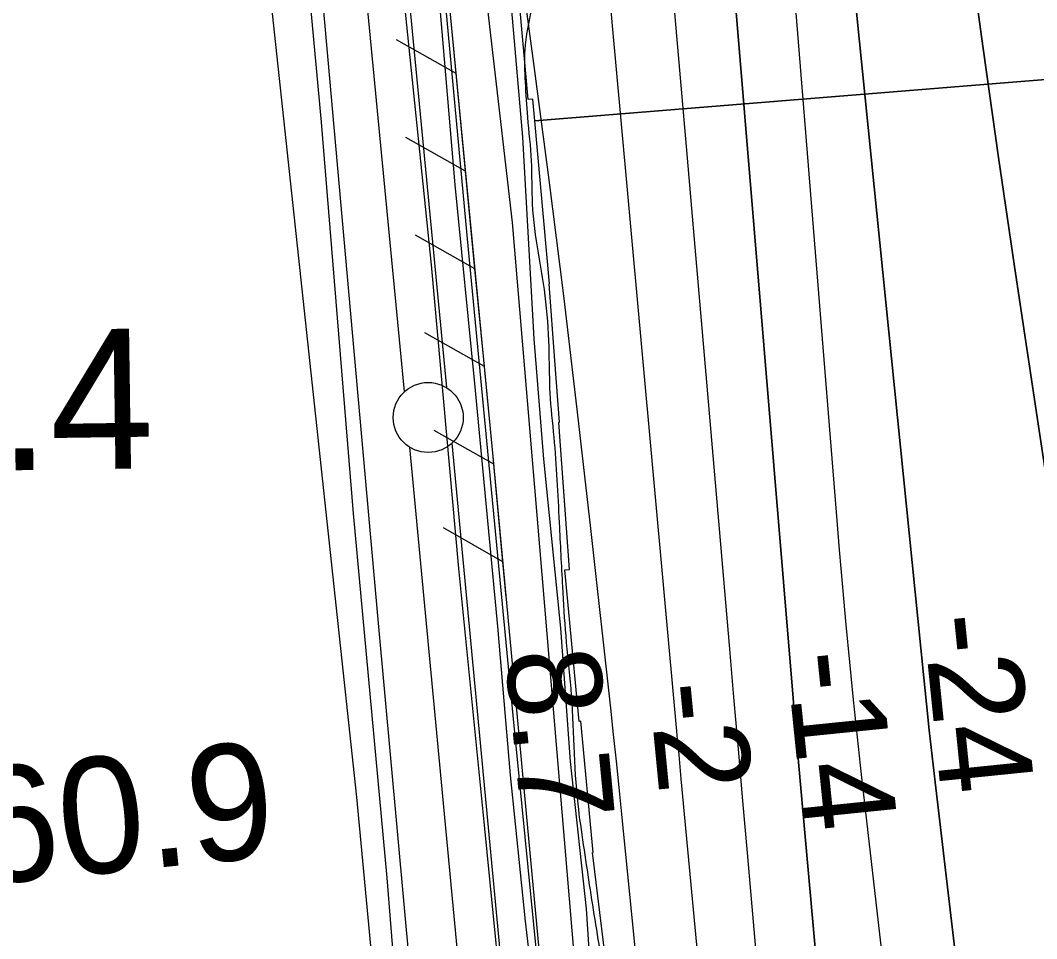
# Model space of a CAD drawing. Extents: x 3694830 to 3732949, y 415201 to 440970.
# Drawn here: x 3715556 to 3716283, y 426007 to 426663 of the extents above; entities that cross this region are included whole.
import ezdxf

# ---------------------------------------------------------------- set-up
doc = ezdxf.new("R2010")
doc.units = 0
for name, color, linetype in [('V-FLOD-BASE', 7, 'Continuous'), ('V-LEVE-TOET', 7, 'Continuous'), ('V-RAIL-TRAK', 7, 'Continuous'), ('V-RIVR-EDGE', 7, 'Continuous'), ('V-RIVR-RANG', 7, 'Continuous'), ('V-RIVR-RANG-IDEN', 7, 'Continuous'), ('V-RRAP-FSHR', 7, 'Continuous'), ('V-RRAP-RVMT', 7, 'Continuous'), ('V-SITE-VEGE', 7, 'Continuous'), ('V-SURV-IDEN', 7, 'Continuous'), ('V-SURV-LINE', 7, 'Continuous'), ('V-TOPO-DPTH', 7, 'Continuous'), ('V-TOPO-MINR', 7, 'Continuous'), ('V-TOPO-WATR', 7, 'Continuous')]:
    doc.layers.add(name, color=color, linetype=linetype)

msp = doc.modelspace()

# ---------------------------------------------------------------- linework, layer by layer
at = {"layer": 'V-FLOD-BASE'}
msp.add_lwpolyline([(3715905.18, 425914.44), (3715887.74, 426090.15), (3715869.81, 426271.15), (3715850.1, 426488.12), (3715831.64, 426668.6), (3715818.42, 426842.69), (3715797.31, 427023.2), (3715781.05, 427212.11), (3715763.21, 427402.63), (3715742.39, 427614.33)], dxfattribs=at)
at = {"layer": 'V-LEVE-TOET'}
for points in [[(3715835.07, 425981.72), (3715811.98, 426234.68), (3715789.9, 426482.35), (3715764.95, 426762.82), (3715743.66, 426980.87), (3715719.56, 427239.13), (3715695.46, 427496.33), (3715669.46, 427778.93)], [(3715760.27, 427687.76), (3715769.43, 427589.85), (3715783.49, 427449.6), (3715793.96, 427321.54), (3715804.19, 427224.16), (3715805.95, 427185.01), (3715809.84, 427147.96), (3715816.68, 427086.03), (3715821.57, 427042.1), (3715826.34, 426984.42), (3715834.02, 426898.69), (3715840.22, 426824.6), (3715841.49, 426789.69), (3715846.98, 426753.16), (3715855.78, 426674.29), (3715866.77, 426545.17), (3715880.82, 426403.33), (3715897.23, 426229.75), (3715906.31, 426123.38), (3715917, 426019.12), (3715930.25, 425906.89)]]:
    msp.add_lwpolyline(points, dxfattribs=at)
at = {"layer": 'V-RAIL-TRAK'}
msp.add_lwpolyline([(3715607.74, 428367.03), (3715620.36, 428242.12), (3715640.52, 428016.68), (3715666.47, 427729.85), (3715694.47, 427434.54), (3715722.17, 427107.51), (3715752.15, 426798.43), (3715771.41, 426589.92), (3715794.26, 426310.52), (3715818.34, 426050.15), (3715838.28, 425800.39), (3715839.84, 425780), (3715843.96, 425726.31), (3715860.4, 425556.95), (3715875.68, 425375.97), (3715892.06, 425199.21), (3715907.36, 425021.41), (3715920.89, 424880.63), (3715944.12, 424642.47), (3715965.27, 424409.62), (3715982.46, 424206.42)], dxfattribs=at)
at = {"layer": 'V-RIVR-EDGE'}
msp.add_spline([(3715510.15, 429495), (3715519.36, 429459.39), (3715532.61, 429419.73), (3715534.19, 429405.98), (3715534.58, 429397.89), (3715533.76, 429394.66), (3715530.11, 429389.82), (3715520.8, 429385.39), (3715520.39, 429383.77), (3715529.22, 429357.06), (3715587.05, 429194.77), (3715589.05, 429189.1), (3715589.84, 429179.8), (3715594.66, 429167.25), (3715599.49, 429156.73), (3715608.37, 429150.64), (3715608.35, 429143.77), (3715610.74, 429128.39), (3715615.55, 429112.21), (3715631.63, 429074.56), (3715650.12, 429029.23), (3715664.58, 428990.37), (3715673.78, 428948.29), (3715681.83, 428932.1), (3715694.71, 428908.61), (3715704.74, 428877.05), (3715710.73, 428847.51), (3715716.69, 428803.42), (3715725.11, 428773.48), (3715730.28, 428739.09), (3715736.62, 428685.3), (3715740.58, 428651.72), (3715742.56, 428635.14), (3715750.16, 428601.96), (3715756.17, 428579.3), (3715763.82, 428567.96), (3715770.28, 428560.67), (3715775.91, 428548.52), (3715779.49, 428526.27), (3715782.29, 428514.14), (3715787.12, 428503.61), (3715794.77, 428492.67), (3715802.44, 428486.59), (3715812.93, 428475.24), (3715818.15, 428463.1), (3715822.56, 428444.08), (3715822.92, 428427.1), (3715822.07, 428409.31), (3715816.37, 428393.55), (3715813.92, 428385.47), (3715810.23, 428364.85), (3715808.57, 428348.28), (3715810.13, 428326.04), (3715814.1, 428296.1), (3715814.88, 428282.35), (3715814.84, 428265.37), (3715813.98, 428246.36), (3715819.15, 428211.98), (3715825.53, 428176.78), (3715828.29, 428148.47), (3715834.3, 428123.39), (3715842.35, 428110.02), (3715849.61, 428100.3), (3715854.02, 428086.14), (3715854.78, 428064.7), (3715853.48, 428030.74), (3715846.1, 427990.72), (3715841.19, 427968.09), (3715841.16, 427956.36), (3715841.13, 427943.83), (3715851.56, 427910.24), (3715867.22, 427862.49), (3715873.62, 427835.78), (3715876, 427815.56), (3715875.96, 427799.38), (3715870.25, 427782.01), (3715868.6, 427769.48), (3715868.57, 427757.35), (3715873.74, 427722.96), (3715882.14, 427684.53), (3715885.3, 427654.6), (3715884.01, 427624.27), (3715879.45, 427578.59), (3715878.15, 427541.39), (3715878.85, 427496.5), (3715875.51, 427454.05), (3715874.59, 427412), (3715872.89, 427377.63), (3715869.55, 427336.4), (3715866.25, 427310.12), (3715865.8, 427291.52), (3715867.35, 427264.02), (3715873.35, 427234.48), (3715883.78, 427200.49), (3715895.01, 427166.5), (3715899.81, 427143.84), (3715900.16, 427120.79), (3715892.8, 427089.27), (3715886.69, 427071.09), (3715883.42, 427055.73), (3715883.37, 427037.94), (3715885.35, 427020.95), (3715899.82, 426986.14), (3715910.27, 426959.02), (3715917.08, 426933.53), (3715925.09, 426900.35), (3715927.85, 426873.65), (3715928.21, 426853.03), (3715928.09, 426806.53), (3715927.57, 426760.83), (3715929.53, 426734.14), (3715927.03, 426703.41), (3715921.69, 426671.48), (3715916.76, 426641.57), (3715917.11, 426618.52), (3715918.67, 426593.45), (3715921.42, 426562.3), (3715922.15, 426531.57), (3715931.69, 426461.59), (3715934.02, 426424.79), (3715934.76, 426396.48), (3715937.51, 426364.93), (3715941.4, 426303.86), (3715943.72, 426258.16), (3715946.06, 426222.98), (3715949.6, 426185.36), (3715954.66, 426102.86), (3715958.63, 426073.73), (3715967.38, 426016.69), (3715974.52, 425960.47), (3715974.86, 425934.18), (3715982.4, 425875.13), (3715987.96, 425832.66), (3715990.72, 425805.15), (3715996.34, 425788.56), (3716003.56, 425763.87), (3716005.53, 425745.27), (3716009.83, 425685.82), (3716014.99, 425646.17), (3716020.14, 425601.68), (3716024.06, 425552.74), (3716029.23, 425516.34), (3716032.8, 425488.43), (3716038.77, 425450.8), (3716039.92, 425423.3), (3716046.66, 425372.74), (3716051.05, 425349.28), (3716057.45, 425317.72), (3716059.8, 425289), (3716060.15, 425266.76), (3716063.71, 425234), (3716070.88, 425189.5), (3716078.08, 425159.56), (3716092.13, 425118.28), (3716107.39, 425074.17), (3716114.99, 425041.8), (3716120.59, 425016.31), (3716122.18, 425002.96), (3716126.07, 424943.91), (3716130, 424894.57), (3716131.17, 424880.01), (3716134.75, 424856.14), (3716142.69, 424795.06), (3716147.47, 424765.13), (3716151.85, 424739.64), (3716155.85, 424721.44), (3716163.09, 424703.22), (3716186.01, 424653.83), (3716195.65, 424627.12), (3716208.91, 424591.5), (3716230.22, 424544.14), (3716256.4, 424502.02), (3716274.11, 424469.22), (3716284.58, 424452.21), (3716301.1, 424424.67), (3716313.57, 424398.36), (3716323.6, 424368.01), (3716332.4, 424330.78), (3716336.38, 424302.87), (3716343.1, 424241.8), (3716348.26, 424202.96), (3716353.46, 424178.69), (3716357.47, 424163.31), (3716373.89, 424099.38), (3716379.45, 424058.53), (3716381.83, 424039.92), (3716383.82, 424027.78), (3716388.23, 424014.43), (3716400.65, 423964.66), (3716419.08, 423899.11), (3716425.48, 423869.57), (3716436.68, 423820.21), (3716441.86, 423786.64), (3716440.58, 423761.16), (3716435.27, 423741.36), (3716429.17, 423726.42), (3716425.12, 423722.79), (3716421.48, 423722.39), (3716417.84, 423723.61), (3716415.42, 423726.05), (3716420.3, 423737.76), (3716418.71, 423748.28), (3716417.12, 423757.18), (3716413.09, 423763.66), (3716404.2, 423765.7), (3716397.33, 423768.14), (3716386.42, 423771.41), (3716379.95, 423773.44), (3716373.08, 423775.08), (3716361.77, 423776.72), (3716353.67, 423774.72), (3716341.52, 423766.26), (3716329.34, 423744.86), (3716320.41, 423731.13), (3716311.83, 423697.19), (3716308.93, 423668.89), (3716306.42, 423653.26)], degree=3, dxfattribs=at)
at = {"layer": 'V-RRAP-FSHR'}
for p, q in [((3715867.79, 426624.73), (3715825.24, 426648.8)), ((3715874.51, 426554.98), (3715831.96, 426579.05)), ((3715881.24, 426485.23), (3715838.69, 426509.29)), ((3715887.96, 426415.47), (3715845.41, 426439.54)), ((3715894.68, 426345.72), (3715852.13, 426369.79)), ((3715901.18, 426275.95), (3715858.7, 426300.14))]:
    msp.add_line(p, q, dxfattribs=at)
for points in [[(3714934.28, 430879.36), (3715310.78, 430066.42), (3715565.7, 429152.28), (3715743.65, 427937.51), (3715907.84, 426518.24), (3715968.15, 425803.52), (3716063.27, 425015.11), (3716110.19, 424867.16), (3716274.4, 424282.95), (3716360.42, 423797.38)], [(3716641.15, 420826.04), (3716497.1, 420943.72), (3716411.63, 421060.5), (3716364.3, 421170.5), (3716321.83, 421303.9), (3716285.1, 421373.79), (3716186.8, 421473.87), (3716066.75, 421590.93), (3715980.47, 421690.03), (3715930.26, 421828.72), (3715913.48, 421896.78), (3715879.02, 422073.91), (3715879.91, 422256.34), (3715873.14, 422428), (3715914.01, 422633.62), (3716031.29, 423135.79), (3716104.08, 423396.54), (3716111.44, 423811.54), (3716102.74, 424148.37), (3716065.57, 424473.12), (3715995.1, 425269.77), (3715894.16, 426351.13), (3715758.55, 427758.05)], [(3715867.79, 426624.73), (3715861.06, 426694.49)], [(3715874.51, 426554.98), (3715867.79, 426624.73)], [(3715881.24, 426485.23), (3715874.51, 426554.98)], [(3715887.96, 426415.47), (3715881.24, 426485.23)], [(3715894.67, 426345.72), (3715894.16, 426351.13), (3715887.96, 426415.47)], [(3715901.18, 426275.95), (3715894.67, 426345.72)], [(3715903.53, 426250.75), (3715901.18, 426275.95)]]:
    msp.add_lwpolyline(points, dxfattribs=at)
at = {"layer": 'V-RRAP-RVMT'}
for points in [[(3715923.96, 426590.93), (3715922.54, 426606.53), (3715919.28, 426606.23), (3715909.32, 426717.59), (3715908.51, 426717.54), (3715907.33, 426739.98), (3715905.23, 426763.26), (3715906.1, 426763.31), (3715901.17, 426857.06), (3715895.02, 426856.77), (3715887.4, 427001.83), (3715882.81, 427001.59), (3715875.31, 427143.64), (3715870.51, 427143.4), (3715862.95, 427286.98), (3715860.57, 427286.83), (3715852.96, 427431.39), (3715847.38, 427431.14), (3715839.75, 427575.95), (3715832.18, 427575.55), (3715824.59, 427719.73)], [(3716281.92, 427611.08), (3716290.16, 427454.44), (3716288.62, 427454.35), (3716295.56, 427322.75), (3716306.06, 427323.31), (3716313.49, 427182.58), (3716341.03, 427184.05), (3716348.65, 427038.99), (3716353.23, 427039.21), (3716361.54, 426881.31), (3716345.04, 426880.46), (3716349.11, 426802.93), (3716366.84, 426804.55), (3716379.75, 426659.97), (3716383.04, 426660.27), (3716385.9, 426628.25), (3715923.96, 426590.93)], [(3716030.61, 425479.43), (3716013.66, 425618.84), (3716021.92, 425619.81), (3716004.86, 425760.58), (3716001.31, 425760.06), (3715982.12, 425917.94), (3715983.48, 425918.1), (3715965.22, 426068.19), (3715965.71, 426068.23), (3715956.81, 426161.98), (3715955.75, 426161.88), (3715945.5, 426270.11), (3715948.81, 426270.36), (3715941.04, 426375.54), (3715941.52, 426375.57), (3715938.26, 426419.75), (3715934.24, 426474.48), (3715934.4, 426474.49), (3715923.96, 426590.93), (3716385.9, 426628.25)]]:
    msp.add_lwpolyline(points, dxfattribs=at)
at = {"layer": 'V-SITE-VEGE'}
for points in [[(3715606.17, 427925.86), (3715661.95, 427410.81), (3715734.62, 426683.35), (3715796.57, 426107.79), (3715824.77, 425809.29)], [(3716021.47, 424979.37), (3715999.43, 425193.84), (3715976.96, 425445.43), (3715950.21, 425736.52), (3715933.97, 425908.39), (3715908.46, 426166.2), (3715876.68, 426499.11), (3715844.95, 426839.74), (3715831.49, 426975.23), (3715810.2, 427186.6), (3715795.4, 427346.85), (3715779.59, 427565.12), (3715754.86, 427823.71)], [(3715851.29, 427197.05), (3715855.56, 427156.02), (3715863.5, 427093.29), (3715870.92, 427058.41), (3715876.78, 427022.78), (3715882.74, 426997.97), (3715884.18, 426985.58), (3715884.64, 426951.54), (3715884.29, 426912.87), (3715886.43, 426892.74), (3715898.94, 426822.23), (3715906.2, 426769.57), (3715906.89, 426675.2), (3715915.3, 426579.2), (3715923.28, 426435.26), (3715930.24, 426349.33), (3715942.29, 426228.55), (3715949.16, 426133.35), (3715960.59, 426028.04), (3715967.39, 425925.88)]]:
    msp.add_lwpolyline(points, dxfattribs=at)
at = {"layer": 'V-SURV-LINE'}
for points in [[(3715678.03, 428299.2), (3715860.84, 426400.37)], [(3715830.98, 426397.48), (3715648.17, 428296.32)], [(3715864.64, 426360.57), (3716046.11, 424440.99)], [(3716016.25, 424438.16), (3715834.77, 426357.75)]]:
    msp.add_lwpolyline(points, dxfattribs=at)
msp.add_circle((3715847.82, 426379.04), 25, dxfattribs=at)
at = {"layer": 'V-TOPO-DPTH'}
for points in [[(3716084.01, 427692.27), (3716114.57, 427523.33), (3716131.11, 427428.85), (3716146.93, 427334.25), (3716161.67, 427239.48), (3716175.68, 427144.59), (3716194.43, 427012.4), (3716198.48, 426983.51), (3716202.47, 426954.62), (3716206.36, 426925.71), (3716210.19, 426896.79), (3716223.03, 426798.6), (3716233.46, 426720.61), (3716244.17, 426642.67), (3716255.33, 426564.78), (3716266.78, 426486.94), (3716310.72, 426193.86), (3716312.81, 426180.21), (3716314.96, 426166.57), (3716317.2, 426152.95), (3716319.49, 426139.33), (3716332.38, 426064.38), (3716341.35, 426013.33), (3716350.58, 425962.33)], [(3716350.58, 425962.33), (3716341.35, 426013.33), (3716332.38, 426064.38), (3716319.49, 426139.33), (3716317.2, 426152.95), (3716314.96, 426166.57), (3716312.81, 426180.21), (3716310.72, 426193.86), (3716266.78, 426486.94), (3716255.33, 426564.78), (3716244.17, 426642.67), (3716233.46, 426720.61), (3716223.03, 426798.6), (3716210.19, 426896.79), (3716206.36, 426925.71), (3716202.47, 426954.62), (3716198.48, 426983.51), (3716194.43, 427012.4), (3716175.68, 427144.59), (3716161.67, 427239.48), (3716146.93, 427334.25), (3716131.11, 427428.85), (3716114.57, 427523.33), (3716084.01, 427692.27)], [(3715896.45, 427655.51), (3715902.85, 427576.57), (3715907.67, 427517.09), (3715912.5, 427457.61), (3715917.32, 427398.13), (3715922.15, 427338.64), (3715948.84, 427009.93), (3715952.55, 426964.8), (3715956.33, 426919.67), (3715960.19, 426874.54), (3715964.12, 426829.43), (3715967.66, 426789.26), (3715973.43, 426724.06), (3715979.25, 426658.87), (3715985.14, 426593.69), (3715991.06, 426528.51), (3716025.22, 426154.94), (3716026, 426146.43), (3716026.79, 426137.93), (3716027.58, 426129.43), (3716028.37, 426120.93), (3716040.7, 425989.75)], [(3716042.78, 427633.46), (3716109.58, 427113.11), (3716113.09, 427084.99), (3716116.49, 427056.85), (3716119.71, 427028.7), (3716122.8, 427000.53), (3716125.72, 426972.33), (3716128.52, 426944.13), (3716131.13, 426915.91), (3716133.63, 426887.68), (3716136.65, 426852.22), (3716140.68, 426806.26), (3716144.85, 426760.32), (3716149.23, 426714.39), (3716153.76, 426668.48), (3716201.78, 426192.93), (3716203.71, 426174.32), (3716205.69, 426155.71), (3716207.77, 426137.11), (3716209.9, 426118.51), (3716232.75, 425923.84)], [(3716232.75, 425923.84), (3716209.9, 426118.51), (3716207.77, 426137.11), (3716205.69, 426155.71), (3716203.71, 426174.32), (3716201.78, 426192.93), (3716153.76, 426668.48), (3716149.23, 426714.39), (3716144.85, 426760.32), (3716140.68, 426806.26), (3716136.65, 426852.22), (3716133.63, 426887.68), (3716131.13, 426915.91), (3716128.52, 426944.13), (3716125.72, 426972.33), (3716122.8, 427000.53), (3716119.71, 427028.7), (3716116.49, 427056.85), (3716113.09, 427084.99), (3716109.58, 427113.11), (3716042.78, 427633.46)], [(3716148.76, 425726.84), (3716114.01, 426114.13), (3716112.59, 426130.22), (3716111.18, 426146.32), (3716109.8, 426162.42), (3716108.45, 426178.52), (3716045.85, 426932.38), (3716008.4, 427415.9), (3716004.45, 427464.44), (3716000.26, 427512.96), (3715995.7, 427561.44), (3715990.89, 427609.9)], [(3716148.76, 425726.84), (3716114.01, 426114.13), (3716112.59, 426130.22), (3716111.18, 426146.32), (3716109.8, 426162.42), (3716108.45, 426178.52), (3716045.85, 426932.38), (3716008.4, 427415.9), (3716004.45, 427464.44), (3716000.26, 427512.96), (3715995.7, 427561.44), (3715990.89, 427609.9)]]:
    msp.add_lwpolyline(points, dxfattribs=at)
at = {"layer": 'V-TOPO-MINR'}
for points in [[(3715952.56, 427703.15), (3715974.16, 427316.31), (3715977.99, 427251.22), (3715982.08, 427186.15), (3715986.56, 427121.1), (3715991.3, 427056.07), (3715997.76, 426971.04), (3715999.5, 426948.54), (3716001.3, 426926.05), (3716003.17, 426903.56), (3716005.09, 426881.08), (3716032.02, 426572.5), (3716038.26, 426500.78), (3716044.48, 426429.05), (3716050.68, 426357.33), (3716056.85, 426285.6), (3716062.8, 426216.34), (3716065.99, 426179.25), (3716069.2, 426142.15), (3716072.42, 426105.05), (3716075.66, 426067.96), (3716091.93, 425881.8)], [(3716084.01, 427692.27), (3716114.57, 427523.33), (3716131.11, 427428.85), (3716146.93, 427334.25), (3716161.67, 427239.48), (3716175.68, 427144.59), (3716194.43, 427012.4), (3716198.48, 426983.51), (3716202.47, 426954.62), (3716206.36, 426925.71), (3716210.19, 426896.79), (3716223.03, 426798.6), (3716233.46, 426720.61), (3716244.17, 426642.67), (3716255.33, 426564.78), (3716266.78, 426486.94), (3716310.72, 426193.86), (3716312.81, 426180.21), (3716314.96, 426166.57), (3716317.2, 426152.95), (3716319.49, 426139.33), (3716332.38, 426064.38), (3716341.35, 426013.33), (3716350.58, 425962.33)], [(3716013.78, 427655.25), (3716033.81, 427481.99), (3716043.98, 427391.51), (3716053.75, 427300.99), (3716062.93, 427210.4), (3716071.72, 427119.78), (3716084.67, 426981.56), (3716086.64, 426960.01), (3716088.56, 426938.45), (3716090.4, 426916.89), (3716092.18, 426895.32), (3716139.18, 426311.34), (3716141.41, 426284.53), (3716143.73, 426257.72), (3716146.19, 426230.92), (3716148.75, 426204.14), (3716151.45, 426177.36), (3716154.24, 426150.6), (3716157.16, 426123.85), (3716160.17, 426097.11), (3716180.73, 425918.68)], [(3715814.76, 427643.31), (3715823.16, 427523.15), (3715829.35, 427442.23), (3715836.25, 427361.38), (3715844.2, 427280.62), (3715852.86, 427199.93), (3715878.96, 426970.82), (3715882.53, 426940.26), (3715886.23, 426909.72), (3715890.1, 426879.19), (3715894.1, 426848.69), (3715923.15, 426631.82), (3715933.97, 426548.88), (3715944.41, 426465.9), (3715954.27, 426382.85), (3715963.75, 426299.76), (3715977.95, 426171.33), (3715980.01, 426152.41), (3715982.03, 426133.48), (3715983.99, 426114.55), (3715985.91, 426095.62), (3716079.54, 425157.19)], [(3716042.78, 427633.46), (3716109.58, 427113.11), (3716113.09, 427084.99), (3716116.49, 427056.85), (3716119.71, 427028.7), (3716122.8, 427000.53), (3716125.72, 426972.33), (3716128.52, 426944.13), (3716131.13, 426915.91), (3716133.63, 426887.68), (3716136.65, 426852.22), (3716140.68, 426806.26), (3716144.85, 426760.32), (3716149.23, 426714.39), (3716153.76, 426668.48), (3716201.78, 426192.93), (3716203.71, 426174.32), (3716205.69, 426155.71), (3716207.77, 426137.11), (3716209.9, 426118.51), (3716232.75, 425923.84)], [(3715990.89, 427609.9), (3715995.7, 427561.44), (3716000.26, 427512.96), (3716004.45, 427464.44), (3716008.4, 427415.9), (3716045.85, 426932.38), (3716108.45, 426178.52), (3716109.8, 426162.42), (3716111.18, 426146.32), (3716112.59, 426130.22), (3716114.01, 426114.13), (3716148.76, 425726.84)]]:
    msp.add_lwpolyline(points, dxfattribs=at)
at = {"layer": 'V-TOPO-WATR'}
msp.add_lwpolyline([(3715896.45, 427655.51), (3715902.85, 427576.57), (3715907.67, 427517.09), (3715912.5, 427457.61), (3715917.32, 427398.13), (3715922.15, 427338.64), (3715948.84, 427009.93), (3715952.55, 426964.8), (3715956.33, 426919.67), (3715960.19, 426874.54), (3715964.12, 426829.43), (3715967.66, 426789.26), (3715973.43, 426724.06), (3715979.25, 426658.87), (3715985.14, 426593.69), (3715991.06, 426528.51), (3716025.22, 426154.94), (3716026, 426146.43), (3716026.79, 426137.93), (3716027.58, 426129.43), (3716028.37, 426120.93), (3716040.7, 425989.75)], dxfattribs=at)

# ---------------------------------------------------------------- texts
at = {"layer": 'V-RIVR-RANG'}
for s, rotation, p in [('-24', 275.81714, (3716201.22, 426236.82)), ('8.7', 275.53833, (3715902.66, 426211.56)), ('-14', 275.81714, (3716103.42, 426210.14)), ('-2', 275.53833, (3716005.41, 426188.1))]:
    msp.add_text(s, height=67, rotation=rotation, dxfattribs=at).set_placement(p)
at = {"layer": 'V-RIVR-RANG-IDEN'}
msp.add_text('R-60.9', height=83, rotation=5.67548, dxfattribs=at).set_placement((3715409.44, 426033.01))
at = {"layer": 'V-SURV-IDEN'}
msp.add_text('1096+97.4', height=100, rotation=0.81346, dxfattribs=at).set_placement((3715016.6, 426333.69))

doc.saveas('drawing.dxf')
